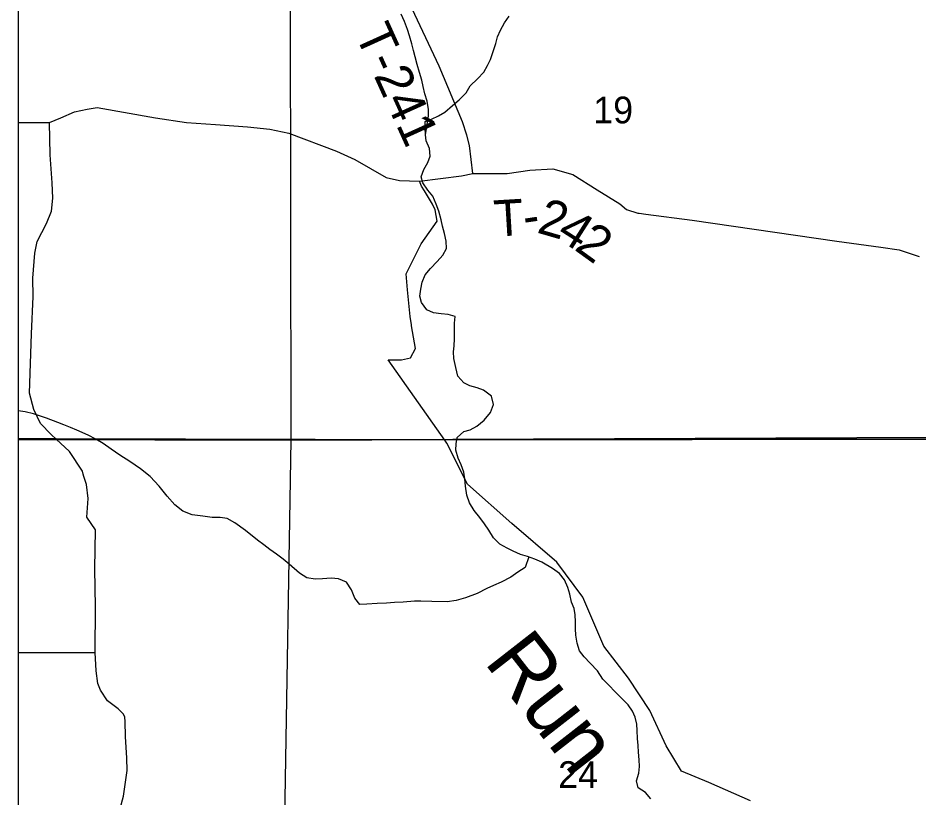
# Model space of a CAD drawing. Extents: x 2.1 to 8.9, y 14.1 to 20.9.
# Drawn here: x 2.1 to 3.51, y 18.588 to 19.809 of the extents above; entities that cross this region are included whole.
import ezdxf

# ---------------------------------------------------------------- set-up
doc = ezdxf.new("R2010")
doc.units = 0
for name, color, linetype in [('Default', 7, 'Continuous'), ('GM_X_City_Street', 7, 'Continuous'), ('GM_X_County_Road_Text', 7, 'Continuous'), ('GM_X_Interchange_Ramps', 7, 'Continuous'), ('GM_X_Minor_River_Text', 7, 'Continuous'), ('PV_P_Text', 7, 'Continuous'), ('SH_Cut_Line', 7, 'Continuous'), ('SH_Data', 7, 'Continuous'), ('TX_P_Misc', 7, 'Continuous')]:
    doc.layers.add(name, color=color, linetype=linetype)

msp = doc.modelspace()

# ---------------------------------------------------------------- linework, layer by layer
at = {"layer": 'Default'}
for p, q in [((2.1, 20.9), (2.1, 19.1502)), ((2.5274, 19.148), (2.526, 20.1453)), ((2.1, 20.144), (2.1, 19.1493)), ((2.1, 19.1502), (2.1, 14.1)), ((2.1596, 19.1501), (2.1, 19.1502)), ((2.1, 19.1502), (2.1596, 19.1501)), ((2.1, 19.1493), (2.5274, 19.148)), ((2.1, 19.1493), (2.1, 18.1363)), ((2.5274, 19.148), (2.1, 19.1493)), ((2.7675, 19.1488), (2.1596, 19.1501)), ((2.1596, 19.1501), (2.7675, 19.1488)), ((2.5107, 18.1291), (2.5274, 19.148)), ((3.624, 19.1497), (2.7675, 19.1488)), ((2.7675, 19.1488), (3.624, 19.1497))]:
    msp.add_line(p, q, dxfattribs=at)
at = {"layer": 'GM_X_City_Street'}
for p, q in [((2.7589, 19.7337), (2.7127, 19.8323)), ((2.7956, 19.6466), (2.7589, 19.7337)), ((2.1886, 19.6622), (2.2083, 19.666)), ((2.2083, 19.666), (2.2238, 19.669)), ((2.2238, 19.669), (2.315, 19.6529)), ((2.1495, 19.6452), (2.1669, 19.6527)), ((2.1669, 19.6527), (2.1886, 19.6622)), ((2.315, 19.6529), (2.3634, 19.6452)), ((2.1, 19.6455), (2.1495, 19.6452)), ((2.1505, 19.5949), (2.1495, 19.6452)), ((2.3634, 19.6452), (2.4088, 19.642)), ((2.4088, 19.642), (2.4592, 19.6385)), ((2.4592, 19.6385), (2.4939, 19.6352)), ((2.8024, 19.6255), (2.7956, 19.6466)), ((2.4939, 19.6352), (2.5237, 19.6288)), ((2.5237, 19.6288), (2.5982, 19.6007)), ((2.8066, 19.6093), (2.8024, 19.6255)), ((2.8118, 19.5653), (2.8066, 19.6093)), ((2.1533, 19.5511), (2.1505, 19.5949)), ((2.5982, 19.6007), (2.627, 19.5874)), ((2.627, 19.5874), (2.6517, 19.5736)), ((2.6517, 19.5736), (2.6762, 19.5592)), ((2.8652, 19.5653), (2.9006, 19.5708)), ((2.9006, 19.5708), (2.9369, 19.5729)), ((2.9369, 19.5729), (2.9683, 19.5642)), ((2.6762, 19.5592), (2.6969, 19.5548)), ((2.6969, 19.5548), (2.7282, 19.5538)), ((2.7282, 19.5538), (2.7938, 19.5617)), ((2.7313, 19.5457), (2.7282, 19.5538)), ((2.7938, 19.5617), (2.8118, 19.5653)), ((2.8118, 19.5653), (2.8652, 19.5653)), ((2.9683, 19.5642), (3.0064, 19.54)), ((2.1543, 19.5269), (2.1533, 19.5511)), ((2.736, 19.5384), (2.7313, 19.5457)), ((2.7377, 19.5357), (2.736, 19.5384)), ((3.0064, 19.54), (3.0415, 19.518)), ((2.1526, 19.5065), (2.1543, 19.5269)), ((2.7487, 19.5177), (2.7377, 19.5357)), ((2.7529, 19.5089), (2.7487, 19.5177)), ((3.0415, 19.518), (3.0521, 19.5094)), ((2.1448, 19.4871), (2.1526, 19.5065)), ((2.7558, 19.4911), (2.7529, 19.5089)), ((3.0521, 19.5094), (3.0697, 19.5037)), ((3.0697, 19.5037), (3.0717, 19.5035)), ((3.0717, 19.5035), (3.0821, 19.5021)), ((3.0821, 19.5021), (3.1549, 19.4923)), ((2.1298, 19.4593), (2.1448, 19.4871)), ((2.7307, 19.4557), (2.7558, 19.4911)), ((3.1549, 19.4923), (3.3814, 19.4598)), ((2.1264, 19.4409), (2.1298, 19.4593)), ((2.7071, 19.4087), (2.7307, 19.4557)), ((3.3814, 19.4598), (3.4499, 19.4503)), ((2.123, 19.4015), (2.1264, 19.4409)), ((3.4499, 19.4503), (3.4788, 19.4459)), ((3.4788, 19.4459), (3.5099, 19.4359)), ((2.1237, 19.3729), (2.123, 19.4015)), ((2.7093, 19.3837), (2.7071, 19.4087)), ((2.7134, 19.3418), (2.7093, 19.3837)), ((2.1212, 19.3147), (2.1237, 19.3729)), ((2.7157, 19.3285), (2.7134, 19.3418)), ((2.7159, 19.3274), (2.7157, 19.3285)), ((2.7221, 19.2916), (2.7159, 19.3274)), ((2.1182, 19.222), (2.1212, 19.3147)), ((2.714, 19.2772), (2.7221, 19.2916)), ((2.7677, 19.1483), (2.679, 19.2742)), ((2.679, 19.2742), (2.6998, 19.2739)), ((2.6998, 19.2739), (2.714, 19.2772)), ((2.125, 19.1961), (2.1182, 19.222)), ((2.135, 19.1741), (2.125, 19.1961)), ((2.1517, 19.157), (2.135, 19.1741)), ((2.1598, 19.1496), (2.1517, 19.157)), ((2.1805, 19.1306), (2.1598, 19.1496)), ((2.7708, 19.1437), (2.7677, 19.1483)), ((2.8034, 19.0792), (2.7708, 19.1437)), ((2.2007, 19.0996), (2.1805, 19.1306)), ((2.2021, 19.095), (2.2007, 19.0996)), ((2.2032, 19.0913), (2.2021, 19.095)), ((2.207, 19.0786), (2.2032, 19.0913)), ((2.2095, 19.0567), (2.207, 19.0786)), ((2.8727, 19.0177), (2.8034, 19.0792)), ((2.2077, 19.0277), (2.2095, 19.0567)), ((2.2211, 19.0079), (2.2077, 19.0277)), ((2.943, 18.9574), (2.8727, 19.0177)), ((2.2202, 18.9471), (2.2211, 19.0079)), ((2.2211, 18.8872), (2.2202, 18.9471)), ((2.9837, 18.9026), (2.943, 18.9574)), ((3.0166, 18.8258), (2.9837, 18.9026)), ((2.2208, 18.8159), (2.2211, 18.8872)), ((3.0551, 18.7755), (3.0166, 18.8258)), ((2.1, 18.816), (2.2208, 18.8159)), ((2.2223, 18.787), (2.2208, 18.8159)), ((2.2251, 18.7673), (2.2223, 18.787)), ((2.229, 18.7569), (2.2251, 18.7673)), ((3.0884, 18.7249), (3.0551, 18.7755)), ((2.2401, 18.7403), (2.229, 18.7569)), ((2.2568, 18.728), (2.2401, 18.7403)), ((2.265, 18.7195), (2.2568, 18.728)), ((3.1142, 18.6699), (3.0884, 18.7249)), ((2.2673, 18.7148), (2.265, 18.7195)), ((2.2677, 18.7081), (2.2673, 18.7148)), ((2.268, 18.6846), (2.2677, 18.7081)), ((2.2703, 18.6507), (2.268, 18.6846)), ((3.1379, 18.6303), (3.1142, 18.6699)), ((2.271, 18.6314), (2.2703, 18.6507)), ((2.2693, 18.6201), (2.271, 18.6314)), ((3.1811, 18.6124), (3.1379, 18.6303)), ((2.2652, 18.5909), (2.2693, 18.6201)), ((3.2459, 18.5838), (3.1811, 18.6124)), ((2.2597, 18.5716), (2.2652, 18.5909))]:
    msp.add_line(p, q, dxfattribs=at)
at = {"layer": 'GM_X_Interchange_Ramps'}
for p, q in [((2.5274, 19.148), (2.526, 20.1453)), ((2.5107, 18.1291), (2.5274, 19.148)), ((3.5387, 19.1524), (2.5274, 19.148)), ((2.5274, 19.148), (3.5387, 19.1524))]:
    msp.add_line(p, q, dxfattribs=at)
at = {"layer": 'SH_Cut_Line'}
msp.add_line((2.1, 20.9), (2.1, 14.1), dxfattribs=at)
at = {"layer": 'SH_Data'}
msp.add_line((2.1, 20.9), (2.1, 14.1), dxfattribs=at)
msp.add_line((2.1, 20.9), (2.1, 14.1), dxfattribs=at)
at = {"layer": 'TX_P_Misc'}
for p, q in [((2.7047, 19.8034), (2.6994, 19.815)), ((2.8611, 19.8011), (2.8683, 19.8116)), ((2.7093, 19.791), (2.7047, 19.8034)), ((2.8549, 19.7898), (2.8611, 19.8011)), ((2.7127, 19.7808), (2.7093, 19.791)), ((2.7161, 19.7684), (2.7127, 19.7808)), ((2.8476, 19.7691), (2.8503, 19.7794)), ((2.8503, 19.7794), (2.8549, 19.7898)), ((2.7187, 19.7578), (2.7161, 19.7684)), ((2.8442, 19.7579), (2.8476, 19.7691)), ((2.7213, 19.748), (2.7187, 19.7578)), ((2.8393, 19.7441), (2.8442, 19.7579)), ((2.7243, 19.7363), (2.7213, 19.748)), ((2.7281, 19.7235), (2.7243, 19.7363)), ((2.8346, 19.7345), (2.8393, 19.7441)), ((2.7316, 19.7118), (2.7281, 19.7235)), ((2.8189, 19.7138), (2.8289, 19.7244)), ((2.8289, 19.7244), (2.8346, 19.7345)), ((2.7338, 19.7016), (2.7316, 19.7118)), ((2.8075, 19.7028), (2.8189, 19.7138)), ((2.7364, 19.6903), (2.7338, 19.7016)), ((2.8014, 19.692), (2.8075, 19.7028)), ((2.7402, 19.6786), (2.7364, 19.6903)), ((2.7799, 19.6719), (2.7903, 19.6806)), ((2.7903, 19.6806), (2.8014, 19.692)), ((2.7421, 19.6658), (2.7402, 19.6786)), ((2.7424, 19.6559), (2.7421, 19.6658)), ((2.7677, 19.6616), (2.7799, 19.6719)), ((2.7377, 19.6261), (2.7424, 19.6559)), ((2.7468, 19.6507), (2.758, 19.6556)), ((2.758, 19.6556), (2.7677, 19.6616)), ((2.737, 19.647), (2.7468, 19.6507)), ((2.737, 19.6363), (2.737, 19.647)), ((2.7377, 19.6261), (2.737, 19.6363)), ((2.7387, 19.6166), (2.7377, 19.6261)), ((2.7437, 19.6046), (2.7387, 19.6166)), ((2.7448, 19.5925), (2.7437, 19.6046)), ((2.7348, 19.572), (2.7413, 19.5829)), ((2.7413, 19.5829), (2.7448, 19.5925)), ((2.731, 19.5605), (2.7348, 19.572)), ((2.7336, 19.5507), (2.731, 19.5605)), ((2.7411, 19.5395), (2.7336, 19.5507)), ((2.749, 19.5299), (2.7411, 19.5395)), ((2.7544, 19.5175), (2.749, 19.5299)), ((2.7585, 19.5066), (2.7544, 19.5175)), ((2.762, 19.493), (2.7585, 19.5066)), ((2.7642, 19.4832), (2.762, 19.493)), ((2.7672, 19.4719), (2.7642, 19.4832)), ((2.7699, 19.4594), (2.7672, 19.4719)), ((2.7702, 19.448), (2.7699, 19.4594)), ((2.7648, 19.438), (2.7702, 19.448)), ((2.7454, 19.4168), (2.756, 19.4278)), ((2.756, 19.4278), (2.7648, 19.438)), ((2.7369, 19.407), (2.7454, 19.4168)), ((2.7323, 19.3955), (2.7369, 19.407)), ((2.7288, 19.3737), (2.7304, 19.3844)), ((2.7304, 19.3844), (2.7323, 19.3955)), ((2.7311, 19.3635), (2.7288, 19.3737)), ((2.7398, 19.3524), (2.7311, 19.3635)), ((2.7502, 19.3474), (2.7398, 19.3524)), ((2.762, 19.3458), (2.7502, 19.3474)), ((2.7731, 19.345), (2.762, 19.3458)), ((2.7838, 19.3416), (2.7731, 19.345)), ((2.783, 19.3313), (2.7838, 19.3416)), ((2.783, 19.3069), (2.783, 19.3313)), ((2.7826, 19.2959), (2.783, 19.3069)), ((2.7814, 19.2864), (2.7826, 19.2959)), ((2.7821, 19.2761), (2.7814, 19.2864)), ((2.7848, 19.2618), (2.7821, 19.2761)), ((2.7883, 19.2482), (2.7848, 19.2618)), ((2.7973, 19.2378), (2.7883, 19.2482)), ((2.807, 19.2335), (2.7973, 19.2378)), ((2.8185, 19.2301), (2.807, 19.2335)), ((2.8285, 19.2266), (2.8185, 19.2301)), ((2.8406, 19.2171), (2.8285, 19.2266)), ((2.844, 19.2039), (2.8406, 19.2171)), ((2.8395, 19.1916), (2.844, 19.2039)), ((2.111, 19.1924), (2.1, 19.194)), ((2.124, 19.1893), (2.111, 19.1924)), ((2.1444, 19.1828), (2.124, 19.1893)), ((2.8296, 19.1795), (2.8395, 19.1916)), ((2.1621, 19.1757), (2.1444, 19.1828)), ((2.1717, 19.1722), (2.1621, 19.1757)), ((2.1821, 19.1683), (2.1717, 19.1722)), ((2.8177, 19.17), (2.8296, 19.1795)), ((2.1921, 19.1641), (2.1821, 19.1683)), ((2.2095, 19.1563), (2.1921, 19.1641)), ((2.7871, 19.1523), (2.7974, 19.1618)), ((2.7974, 19.1618), (2.8072, 19.1643)), ((2.8072, 19.1643), (2.8177, 19.17)), ((2.2218, 19.1498), (2.2095, 19.1563)), ((2.2331, 19.1429), (2.2218, 19.1498)), ((2.7855, 19.1424), (2.7871, 19.1523)), ((2.2455, 19.1342), (2.2331, 19.1429)), ((2.2591, 19.1247), (2.2455, 19.1342)), ((2.785, 19.1328), (2.7855, 19.1424)), ((2.7885, 19.12), (2.785, 19.1328)), ((2.275, 19.115), (2.2591, 19.1247)), ((2.7934, 19.1095), (2.7885, 19.12)), ((2.2917, 19.1033), (2.275, 19.115)), ((2.3069, 19.0913), (2.2917, 19.1033)), ((2.7975, 19.0979), (2.7934, 19.1095)), ((2.3207, 19.0761), (2.3069, 19.0913)), ((2.799, 19.0876), (2.7975, 19.0979)), ((2.8001, 19.0763), (2.799, 19.0876)), ((2.3334, 19.0605), (2.3207, 19.0761)), ((2.8021, 19.0619), (2.8001, 19.0763)), ((2.3456, 19.0468), (2.3334, 19.0605)), ((2.8066, 19.0499), (2.8021, 19.0619)), ((2.3577, 19.0369), (2.3456, 19.0468)), ((2.8135, 19.0383), (2.8066, 19.0499)), ((2.3727, 19.0313), (2.3577, 19.0369)), ((2.3891, 19.0292), (2.3727, 19.0313)), ((2.8226, 19.0272), (2.8135, 19.0383)), ((2.4036, 19.0274), (2.3891, 19.0292)), ((2.4162, 19.027), (2.4036, 19.0274)), ((2.4272, 19.0254), (2.4162, 19.027)), ((2.4392, 19.019), (2.4272, 19.0254)), ((2.456, 19.0066), (2.4392, 19.019)), ((2.8301, 19.0175), (2.8226, 19.0272)), ((2.8369, 19.0074), (2.8301, 19.0175)), ((2.4747, 18.9916), (2.456, 19.0066)), ((2.8437, 18.9955), (2.8369, 19.0074)), ((2.4844, 18.9842), (2.4747, 18.9916)), ((2.8539, 18.9852), (2.8437, 18.9955)), ((2.4941, 18.9773), (2.4844, 18.9842)), ((2.5042, 18.9697), (2.4941, 18.9773)), ((2.8651, 18.979), (2.8539, 18.9852)), ((2.8748, 18.9744), (2.8651, 18.979)), ((2.8863, 18.9694), (2.8748, 18.9744)), ((2.5148, 18.962), (2.5042, 18.9697)), ((2.5245, 18.9543), (2.5148, 18.962)), ((2.8971, 18.966), (2.8863, 18.9694)), ((2.899, 18.9654), (2.8934, 18.9487)), ((2.9086, 18.9621), (2.8971, 18.966)), ((2.9198, 18.9572), (2.9086, 18.9621)), ((2.5405, 18.94), (2.5245, 18.9543)), ((2.8934, 18.9487), (2.8819, 18.9415)), ((2.9364, 18.9474), (2.9198, 18.9572)), ((2.947, 18.9394), (2.9364, 18.9474)), ((2.5518, 18.9327), (2.5405, 18.94)), ((2.5651, 18.9309), (2.5518, 18.9327)), ((2.5898, 18.9324), (2.5765, 18.9312)), ((2.6013, 18.9312), (2.5898, 18.9324)), ((2.8711, 18.934), (2.8561, 18.9259)), ((2.8819, 18.9415), (2.8711, 18.934)), ((2.9549, 18.9294), (2.947, 18.9394)), ((2.5765, 18.9312), (2.5651, 18.9309)), ((2.614, 18.9259), (2.6013, 18.9312)), ((2.6216, 18.914), (2.614, 18.9259)), ((2.8441, 18.921), (2.8336, 18.9161)), ((2.8561, 18.9259), (2.8441, 18.921)), ((2.9602, 18.9174), (2.9549, 18.9294)), ((2.6269, 18.9009), (2.6216, 18.914)), ((2.8183, 18.908), (2.8003, 18.9013)), ((2.8336, 18.9161), (2.8183, 18.908)), ((2.9632, 18.9072), (2.9602, 18.9174)), ((2.9662, 18.8947), (2.9632, 18.9072)), ((2.6348, 18.8912), (2.6269, 18.9009)), ((2.6458, 18.8916), (2.6348, 18.8912)), ((2.6618, 18.8928), (2.6458, 18.8916)), ((2.6766, 18.8933), (2.6618, 18.8928)), ((2.6891, 18.8941), (2.6766, 18.8933)), ((2.7028, 18.8949), (2.6891, 18.8941)), ((2.7206, 18.8962), (2.7028, 18.8949)), ((2.7301, 18.8965), (2.7206, 18.8962)), ((2.7476, 18.8955), (2.7301, 18.8965)), ((2.7712, 18.8951), (2.7476, 18.8955)), ((2.7856, 18.8974), (2.7712, 18.8951)), ((2.8003, 18.9013), (2.7856, 18.8974)), ((2.97, 18.8846), (2.9662, 18.8947)), ((2.9718, 18.8747), (2.97, 18.8846)), ((2.9725, 18.8641), (2.9718, 18.8747)), ((2.9725, 18.8531), (2.9725, 18.8641)), ((2.9728, 18.8428), (2.9725, 18.8531)), ((2.9747, 18.8307), (2.9728, 18.8428)), ((2.9785, 18.8187), (2.9747, 18.8307)), ((2.9856, 18.809), (2.9785, 18.8187)), ((2.9954, 18.799), (2.9856, 18.809)), ((3.0065, 18.7872), (2.9954, 18.799)), ((3.0152, 18.7742), (3.0065, 18.7872)), ((3.0243, 18.7646), (3.0152, 18.7742)), ((3.0341, 18.7542), (3.0243, 18.7646)), ((3.0439, 18.745), (3.0341, 18.7542)), ((3.0545, 18.7339), (3.0439, 18.745)), ((3.0616, 18.7243), (3.0545, 18.7339)), ((3.0657, 18.7145), (3.0616, 18.7243)), ((3.068, 18.7039), (3.0657, 18.7145)), ((3.0687, 18.6937), (3.068, 18.7039)), ((3.0694, 18.6812), (3.0687, 18.6937)), ((3.0702, 18.6701), (3.0694, 18.6812)), ((3.0709, 18.6599), (3.0702, 18.6701)), ((3.072, 18.6481), (3.0709, 18.6599)), ((3.0711, 18.6272), (3.0723, 18.6375)), ((3.0723, 18.6375), (3.072, 18.6481)), ((3.0677, 18.6153), (3.0711, 18.6272)), ((3.0703, 18.604), (3.0677, 18.6153)), ((3.0816, 18.5967), (3.0703, 18.604)), ((3.0903, 18.5867), (3.0816, 18.5967))]:
    msp.add_line(p, q, dxfattribs=at)

# ---------------------------------------------------------------- texts
at = {"layer": 'GM_X_County_Road_Text'}
for s, p in [('19', (3.0001, 19.644)), ('24', (2.9451, 18.6039))]:
    msp.add_text(s, height=0.04186, rotation=0, dxfattribs=at).set_placement(p)
at = {"layer": 'GM_X_Minor_River_Text'}
for s, height, rotation, p in [('T-241', 0.05682, 294.3793, (2.6265, 19.7843)), ('T', 0.0568, 3.452, (2.846, 19.4666)), ('2', 0.0568, 343.853, (2.9103, 19.4735)), ('-', 0.0568, 8.2953, (2.8936, 19.4697)), ('4', 0.0568, 327.4965, (2.9401, 19.4655)), ('2', 0.0568, 324.1012, (2.9688, 19.4472))]:
    msp.add_text(s, height=height, rotation=rotation, dxfattribs=at).set_placement(p)
at = {"layer": 'PV_P_Text'}
msp.add_text('Run', height=0.09471, rotation=307.955, dxfattribs=at).set_placement((2.8279, 18.801))

doc.saveas('drawing.dxf')
